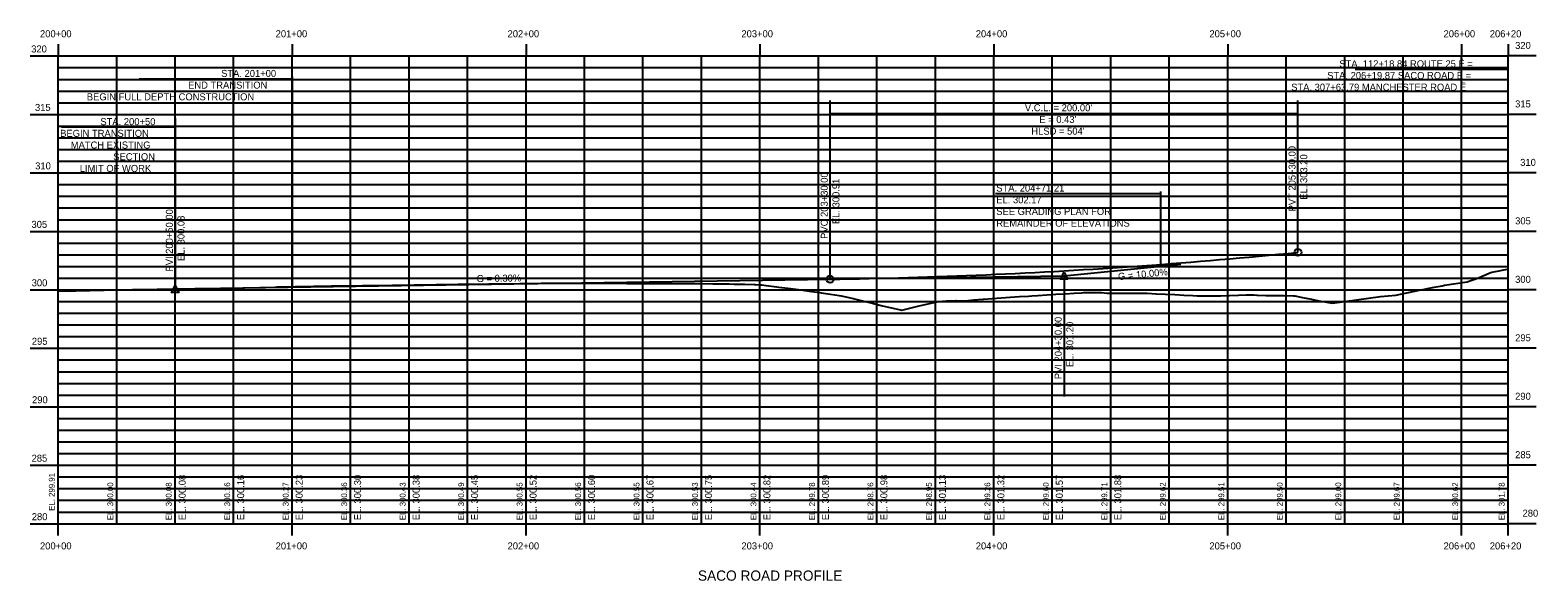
# Model space of a CAD drawing. Extents: x 916064 to 2216531, y 210276 to 327856.
# Drawn here: x 916107 to 916752, y 326074 to 326309 of the extents above; entities that cross this region are included whole.
import ezdxf

# ---------------------------------------------------------------- set-up
doc = ezdxf.new("R2010")
doc.units = 0
for name, color, linetype in [('ANNOTATION', 7, 'Continuous'), ('BARRIER', 7, 'Continuous'), ('D_Roadway_Centerline', 7, 'Continuous'), ('D_Roadway_Centerline_Bearings', 7, 'Continuous'), ('D_Roadway_Centerline_CurveData', 7, 'Continuous'), ('D_Roadway_Centerline_Flags', 7, 'Continuous'), ('D_Roadway_Centerline_Text', 7, 'Continuous'), ('D_Roadway_Edge_Pavement', 7, 'Continuous')]:
    doc.layers.add(name, color=color, linetype=linetype)

msp = doc.modelspace()

# ---------------------------------------------------------------- linework, layer by layer
at = {"layer": 'ANNOTATION'}
msp.add_line((916169.09, 326198.47), (916449.09, 326202.6), dxfattribs=at)
for points in [[(916449.09, 326202.6), (916453.26, 326202.66), (916457.42, 326202.73), (916461.59, 326202.81), (916465.76, 326202.9), (916469.92, 326203), (916474.09, 326203.1), (916478.26, 326203.21), (916482.42, 326203.33), (916486.59, 326203.45), (916490.76, 326203.58), (916494.92, 326203.72), (916499.09, 326203.87), (916503.26, 326204.02), (916507.42, 326204.18), (916511.59, 326204.35), (916515.76, 326204.53), (916519.92, 326204.71), (916524.09, 326204.9), (916528.26, 326205.1), (916532.42, 326205.31), (916536.59, 326205.52), (916540.76, 326205.74), (916544.92, 326205.97), (916553.26, 326206.45), (916557.42, 326206.7), (916561.59, 326206.95), (916565.76, 326207.22), (916569.92, 326207.49), (916574.09, 326207.77), (916578.26, 326208.06), (916582.42, 326208.35), (916586.59, 326208.65), (916590.49, 326208.94)], [(916590.49, 326208.94), (916590.76, 326208.96), (916594.92, 326209.28), (916599.09, 326209.6), (916603.26, 326209.94), (916607.42, 326210.28), (916611.59, 326210.62), (916615.76, 326210.98), (916619.92, 326211.34), (916624.09, 326211.71), (916628.26, 326212.08), (916632.42, 326212.46), (916636.59, 326212.86), (916640.76, 326213.25), (916644.92, 326213.66), (916649.09, 326214.07)]]:
    msp.add_lwpolyline(points, dxfattribs=at)
at = {"layer": 'D_Roadway_Centerline'}
for p, q in [((916107.09, 326298.06), (916119.09, 326298.06)), ((916107.09, 326298.06), (916119.09, 326298.06)), ((916119.09, 326303.06), (916119.09, 326298.06)), ((916119.09, 326298.06), (916738.96, 326298.06)), ((916119.09, 326098.06), (916119.09, 326298.06)), ((916219.09, 326303.06), (916219.09, 326298.06)), ((916219.09, 326098.06), (916219.09, 326298.06)), ((916319.09, 326303.06), (916319.09, 326298.06)), ((916319.09, 326098.06), (916319.09, 326298.06)), ((916419.09, 326303.06), (916419.09, 326298.06)), ((916419.09, 326098.06), (916419.09, 326298.06)), ((916519.09, 326303.06), (916519.09, 326298.06)), ((916519.09, 326098.06), (916519.09, 326298.06)), ((916619.09, 326303.06), (916619.09, 326298.06)), ((916619.09, 326098.06), (916619.09, 326298.06)), ((916719.09, 326303.06), (916719.09, 326298.06)), ((916719.09, 326098.06), (916719.09, 326298.06)), ((916738.96, 326303.06), (916738.96, 326298.06)), ((916738.96, 326098.06), (916738.96, 326298.06)), ((916750.96, 326298.06), (916738.96, 326298.06)), ((916750.96, 326298.06), (916738.96, 326298.06)), ((916107.09, 326273.06), (916119.09, 326273.06)), ((916119.09, 326273.06), (916738.96, 326273.06)), ((916750.96, 326273.06), (916738.96, 326273.06)), ((916107.09, 326248.06), (916119.09, 326248.06)), ((916119.09, 326248.06), (916738.96, 326248.06)), ((916750.96, 326248.06), (916738.96, 326248.06)), ((916107.09, 326223.06), (916119.09, 326223.06)), ((916119.09, 326223.06), (916738.96, 326223.06)), ((916750.96, 326223.06), (916738.96, 326223.06)), ((916107.09, 326198.06), (916119.09, 326198.06)), ((916119.09, 326198.06), (916738.96, 326198.06)), ((916750.96, 326198.06), (916738.96, 326198.06)), ((916107.09, 326173.06), (916119.09, 326173.06)), ((916119.09, 326173.06), (916738.96, 326173.06)), ((916750.96, 326173.06), (916738.96, 326173.06)), ((916107.09, 326148.06), (916119.09, 326148.06)), ((916119.09, 326148.06), (916738.96, 326148.06)), ((916750.96, 326148.06), (916738.96, 326148.06)), ((916107.09, 326123.06), (916119.09, 326123.06)), ((916119.09, 326123.06), (916738.96, 326123.06)), ((916750.96, 326123.06), (916738.96, 326123.06)), ((916107.09, 326098.06), (916119.09, 326098.06)), ((916119.09, 326098.06), (916738.96, 326098.06)), ((916119.09, 326093.06), (916119.09, 326098.06)), ((916219.09, 326093.06), (916219.09, 326098.06)), ((916319.09, 326093.06), (916319.09, 326098.06)), ((916419.09, 326093.06), (916419.09, 326098.06)), ((916519.09, 326093.06), (916519.09, 326098.06)), ((916619.09, 326093.06), (916619.09, 326098.06)), ((916719.09, 326093.06), (916719.09, 326098.06)), ((916750.96, 326098.06), (916738.96, 326098.06)), ((916738.96, 326093.06), (916738.96, 326098.06))]:
    msp.add_line(p, q, dxfattribs=at)
at = {"layer": 'D_Roadway_Centerline_Bearings'}
for p, q in [((916449.09, 326202.6), (916449.09, 326279)), ((916649.09, 326214.07), (916649.09, 326279)), ((916449.09, 326227.6), (916449.09, 326275.2)), ((916169.09, 326198.47), (916169.09, 326246.06)), ((916649.09, 326214.07), (916649.09, 326239.07)), ((916449.09, 326202.6), (916449.09, 326227.6)), ((916549.09, 326204.07), (916599.09, 326209.07)), ((916499.09, 326203.33), (916549.09, 326204.07)), ((916549.09, 326204.07), (916549.09, 326152.47))]:
    msp.add_line(p, q, dxfattribs=at)
msp.add_lwpolyline([(916449.09, 326273.42), (916649.09, 326273.42)], dxfattribs=at)
for points in [[(916549.09, 326205.57), (916550.59, 326202.57), (916547.59, 326202.57)], [(916169.09, 326199.97), (916170.59, 326196.97), (916167.59, 326196.97)]]:
    msp.add_lwpolyline(points, close=True, dxfattribs=at)
for centre in [(916649.09, 326214.07), (916449.09, 326202.6)]:
    msp.add_circle(centre, 1.5, dxfattribs=at)
at = {"layer": 'D_Roadway_Centerline_Flags'}
msp.add_lwpolyline([(916119.09, 326197.59), (916124.98, 326197.68), (916126.58, 326197.68), (916150.89, 326198.19), (916152.14, 326198.22), (916153.33, 326198.23), (916177.49, 326198.59), (916178.18, 326198.59), (916192.26, 326198.84), (916211.71, 326199.25), (916212.15, 326199.27), (916212.66, 326199.28), (916235.99, 326199.75), (916236.3, 326199.76), (916262.05, 326200.11), (916289.87, 326200.46), (916316.43, 326200.76), (916317.93, 326200.78), (916318.19, 326200.78), (916321.02, 326200.81), (916324.13, 326200.84), (916325.6, 326200.85), (916330.18, 326200.86), (916334.76, 326200.86), (916339.34, 326200.86), (916343.92, 326200.86), (916345.96, 326200.85), (916348.5, 326200.86), (916353.08, 326200.85), (916357.66, 326200.85), (916362.24, 326200.84), (916366.11, 326200.82), (916366.82, 326200.82), (916371.4, 326200.79), (916373.46, 326200.77), (916375.98, 326200.78), (916380.56, 326200.8), (916385.14, 326200.82), (916386.98, 326200.83), (916389.72, 326200.79), (916394.3, 326200.73), (916398.89, 326200.65), (916400.65, 326200.62), (916403.47, 326200.6), (916405.89, 326200.58), (916408.05, 326200.55), (916412.63, 326200.47), (916416.81, 326200.39), (916417.21, 326200.37), (916419.11, 326200.24), (916419.94, 326200.2), (916421.79, 326199.97), (916426.37, 326199.36), (916427.16, 326199.25), (916430.95, 326198.78), (916435.53, 326198.18), (916440.11, 326197.55), (916444.69, 326196.89), (916445.2, 326196.82), (916449.27, 326196.21), (916453, 326195.62), (916453.85, 326195.47), (916454.6, 326195.34), (916458.43, 326194.45), (916463.01, 326193.35), (916467.59, 326192.22), (916471.5, 326191.26), (916475.4, 326190.34), (916479.22, 326189.46), (916479.3, 326189.44), (916479.73, 326189.34), (916480.38, 326189.51), (916483.21, 326190.22), (916487.11, 326191.18), (916491.01, 326192.09), (916494.92, 326192.98), (916495.39, 326193.08), (916498.82, 326193.29), (916502.72, 326193.51), (916502.95, 326193.53), (916506.63, 326193.41), (916506.75, 326193.41), (916510.53, 326193.72), (916514.43, 326194.04), (916514.86, 326194.08), (916518.34, 326194.33), (916522.24, 326194.6), (916526.14, 326194.87), (916530.05, 326195.14), (916533.95, 326195.4), (916535.28, 326195.49), (916537.85, 326195.66), (916541.76, 326195.91), (916545.66, 326196.16), (916549.56, 326196.4), (916553.47, 326196.64), (916556.68, 326196.84), (916557.37, 326196.85), (916561.27, 326196.92), (916564.78, 326196.97), (916565.18, 326196.92), (916567.36, 326196.63), (916569.08, 326196.63), (916571.18, 326196.62), (916572.98, 326196.63), (916576.89, 326196.64), (916580.79, 326196.64), (916583.36, 326196.64), (916584.69, 326196.58), (916588.54, 326196.4), (916588.6, 326196.39), (916592.5, 326196.22), (916596.4, 326196.03), (916600.31, 326195.84), (916604.21, 326195.65), (916606.08, 326195.55), (916608.11, 326195.54), (916612.02, 326195.5), (916615.92, 326195.47), (916615.95, 326195.47), (916619.82, 326195.63), (916623.73, 326195.79), (916626.97, 326195.91), (916627.63, 326195.92), (916630.18, 326195.97), (916631.53, 326195.75), (916631.76, 326195.71), (916635.44, 326195.68), (916639.34, 326195.63), (916643.24, 326195.57), (916647.15, 326195.5), (916647.76, 326195.49), (916651.05, 326194.85), (916654.95, 326194.06), (916658.01, 326193.42), (916663.94, 326192.33), (916684.38, 326195.26), (916691, 326195.74), (916701.03, 326197.95), (916707.41, 326199.26), (916710.74, 326199.82), (916711.81, 326200.04), (916721.42, 326201.54), (916722.95, 326201.99), (916725.18, 326202.78), (916729.55, 326204.55), (916731.18, 326205.35), (916732.03, 326205.61), (916735.16, 326206.24), (916736.36, 326206.44), (916738.66, 326206.92), (916738.96, 326206.98)], dxfattribs=at)
at = {"layer": 'D_Roadway_Centerline_Text'}
for p, q in [((916144.09, 326098.06), (916144.09, 326298.06)), ((916169.09, 326098.06), (916169.09, 326298.06)), ((916194.09, 326098.06), (916194.09, 326298.06)), ((916244.09, 326098.06), (916244.09, 326298.06)), ((916269.09, 326098.06), (916269.09, 326298.06)), ((916294.09, 326098.06), (916294.09, 326298.06)), ((916344.09, 326098.06), (916344.09, 326298.06)), ((916369.09, 326098.06), (916369.09, 326298.06)), ((916394.09, 326098.06), (916394.09, 326298.06)), ((916444.09, 326098.06), (916444.09, 326298.06)), ((916469.09, 326098.06), (916469.09, 326298.06)), ((916494.09, 326098.06), (916494.09, 326298.06)), ((916544.09, 326098.06), (916544.09, 326298.06)), ((916569.09, 326098.06), (916569.09, 326298.06)), ((916594.09, 326098.06), (916594.09, 326298.06)), ((916644.09, 326098.06), (916644.09, 326298.06)), ((916669.09, 326098.06), (916669.09, 326298.06)), ((916694.09, 326098.06), (916694.09, 326298.06)), ((916119.09, 326293.06), (916738.96, 326293.06)), ((916119.09, 326288.06), (916738.96, 326288.06)), ((916119.09, 326283.06), (916738.96, 326283.06)), ((916119.09, 326278.06), (916738.96, 326278.06)), ((916119.09, 326268.06), (916738.96, 326268.06)), ((916119.09, 326263.06), (916738.96, 326263.06)), ((916119.09, 326258.06), (916738.96, 326258.06)), ((916119.09, 326253.06), (916738.96, 326253.06)), ((916119.09, 326243.06), (916738.96, 326243.06)), ((916119.09, 326238.06), (916738.96, 326238.06)), ((916119.09, 326233.06), (916738.96, 326233.06)), ((916119.09, 326228.06), (916738.96, 326228.06)), ((916119.09, 326218.06), (916738.96, 326218.06)), ((916119.09, 326213.06), (916738.96, 326213.06)), ((916119.09, 326208.06), (916738.96, 326208.06)), ((916119.09, 326203.06), (916738.96, 326203.06)), ((916119.09, 326193.06), (916738.96, 326193.06)), ((916119.09, 326188.06), (916738.96, 326188.06)), ((916119.09, 326183.06), (916738.96, 326183.06)), ((916119.09, 326178.06), (916738.96, 326178.06)), ((916119.09, 326168.06), (916738.96, 326168.06)), ((916119.09, 326163.06), (916738.96, 326163.06)), ((916119.09, 326158.06), (916738.96, 326158.06)), ((916119.09, 326153.06), (916738.96, 326153.06)), ((916119.09, 326143.06), (916738.96, 326143.06)), ((916119.09, 326138.06), (916738.96, 326138.06)), ((916119.09, 326133.06), (916738.96, 326133.06)), ((916119.09, 326128.06), (916738.96, 326128.06)), ((916119.09, 326118.06), (916738.96, 326118.06)), ((916119.09, 326113.06), (916738.96, 326113.06)), ((916119.09, 326108.06), (916738.96, 326108.06)), ((916119.09, 326103.06), (916738.96, 326103.06))]:
    msp.add_line(p, q, dxfattribs=at)
at = {"layer": 'D_Roadway_Edge_Pavement'}
for p, q in [((916673.62, 326292.43), (916738.96, 326292.43)), ((916153.75, 326288.32), (916219.09, 326288.32)), ((916219.09, 326289.07), (916219.09, 326199.2)), ((916120.55, 326267.71), (916169.09, 326267.71)), ((916169.09, 326271.48), (916169.09, 326198.47)), ((916590.3, 326240.04), (916590.3, 326208.93)), ((916519.76, 326239.29), (916590.3, 326239.29))]:
    msp.add_line(p, q, dxfattribs=at)

# ---------------------------------------------------------------- texts
at = {"layer": 'BARRIER'}
for s, p in [('EL. 300.08', (916173.59, 326099.56)), ('EL. 300.16', (916198.59, 326099.56)), ('EL. 300.23', (916223.59, 326099.56)), ('EL. 300.30', (916248.59, 326099.56)), ('EL. 300.38', (916273.59, 326099.56)), ('EL. 300.45', (916298.59, 326099.56)), ('EL. 300.52', (916323.59, 326099.56)), ('EL. 300.60', (916348.59, 326099.56)), ('EL. 300.67', (916373.59, 326099.56)), ('EL. 300.75', (916398.59, 326099.56)), ('EL. 300.82', (916423.59, 326099.56)), ('EL. 300.89', (916448.59, 326099.56)), ('EL. 300.98', (916473.59, 326099.56)), ('EL. 301.13', (916498.59, 326099.56)), ('EL. 301.32', (916523.59, 326099.56)), ('EL. 301.57', (916548.59, 326099.56)), ('EL. 301.88', (916573.59, 326099.56))]:
    msp.add_text(s, height=3, rotation=90, dxfattribs=at).set_placement(p)
at = {"layer": 'D_Roadway_Centerline_Bearings'}
for s, p in [("V.C.L. = 200.00'", (916532.36, 326274.42)), ("E = 0.43'", (916538.54, 326269.42)), ("HLSD = 504'", (916535.13, 326264.42))]:
    msp.add_text(s, height=3, dxfattribs=at).set_placement(p)
for s, rotation, p in [('PVT 205+30.00', 90, (916648.09, 326231.58)), ('EL. 303.20', 90, (916653.09, 326236.61)), ('PVC 203+30.00', 90, (916448.09, 326219.86)), ('EL. 300.91', 90, (916453.09, 326226.18)), ('PVI 200+50.00', 90, (916168.09, 326205.88)), ('EL. 300.08', 90, (916173.09, 326210.37)), ('G = 0.30%', 0.84525, (916297.98, 326201.37)), ('PVI 204+30.00', 90, (916548.09, 326159.86)), ('EL. 301.20', 90, (916553.09, 326165.01))]:
    msp.add_text(s, height=3, rotation=rotation, dxfattribs=at).set_placement(p)
at = {"layer": 'D_Roadway_Centerline_CurveData'}
for s, height, p in [('200+00', 3, (916111.3, 326306.06)), ('201+00', 3, (916212.05, 326306.06)), ('202+00', 3, (916311.2, 326306.06)), ('203+00', 3, (916411.17, 326306.06)), ('204+00', 3, (916511.36, 326306.06)), ('205+00', 3, (916611.25, 326306.06)), ('206+00', 3, (916711.36, 326306.06)), ('206+20', 3, (916731.12, 326306.06)), ('320', 3, (916107.53, 326299.56)), ('320', 3, (916107.53, 326299.56)), ('320', 3, (916741.96, 326301.06)), ('320', 3, (916741.96, 326301.06)), ('315', 3, (916741.96, 326276.06)), ('315', 3, (916109.16, 326274.56)), ('310', 3, (916744.13, 326251.06)), ('310', 3, (916109.24, 326249.56)), ('305', 3, (916107.66, 326224.56)), ('305', 3, (916741.96, 326226.06)), ('300', 3, (916107.74, 326199.56)), ('300', 3, (916741.96, 326201.06)), ('295', 3, (916107.82, 326174.56)), ('295', 3, (916741.96, 326176.06)), ('290', 3, (916107.9, 326149.56)), ('290', 3, (916741.96, 326151.06)), ('285', 3, (916107.71, 326124.56)), ('285', 3, (916741.96, 326126.06)), ('280', 3, (916107.79, 326099.56)), ('280', 3, (916745.13, 326101.06)), ('200+00', 3, (916111.3, 326087.06)), ('201+00', 3, (916212.05, 326087.06)), ('202+00', 3, (916311.2, 326087.06)), ('203+00', 3, (916411.17, 326087.06)), ('204+00', 3, (916511.36, 326087.06)), ('205+00', 3, (916611.25, 326087.06)), ('206+00', 3, (916711.36, 326087.06)), ('206+20', 3, (916731.12, 326087.06)), ('SACO ROAD PROFILE', 4.3749, (916392.58, 326073.68))]:
    msp.add_text(s, height=height, dxfattribs=at).set_placement(p)
at = {"layer": 'D_Roadway_Edge_Pavement'}
for s, p in [('STA. 201+00', (916188.72, 326289.1)), ('STA. 206+19.87 SACO ROAD Ë =', (916661.59, 326288.21)), ('STA. 112+18.84 ROUTE 25 Ë =', (916666.79, 326293.21)), ('END TRANSITION', (916174.62, 326284.1)), ('STA. 307+63.79 MANCHESTER ROAD Ë', (916646.21, 326283.21)), ('BEGIN FULL DEPTH CONSTRUCTION', (916131.32, 326279.1)), ('BEGIN TRANSITION', (916119.92, 326263.48)), ('STA. 200+50', (916137.11, 326268.48)), ('MATCH EXISTING', (916124.45, 326258.48)), (' SECTION', (916141.51, 326253.48)), ('LIMIT OF WORK', (916128.29, 326248.48)), ('STA. 204+71.21', (916520.13, 326240.07)), ('EL. 302.17', (916520.13, 326235.07)), ('SEE GRADING PLAN FOR', (916520.13, 326230.07)), ('REMAINDER OF ELEVATIONS', (916520.13, 326225.07))]:
    msp.add_text(s, height=3, dxfattribs=at).set_placement(p)
for s, height, rotation, p in [('G = 10.00%', 3, 5.71059, (916572.35, 326202.21)), ('EL. 299.91', 2.5, 90, (916117.59, 326103.56)), ('EL. 300.00', 2.5, 90, (916142.59, 326099.56)), ('EL. 300.08', 2.5, 90, (916167.59, 326099.56)), ('EL. 300.16', 2.5, 90, (916192.59, 326099.56)), ('EL. 300.27', 2.5, 90, (916217.59, 326099.56)), ('EL. 300.36', 2.5, 90, (916242.59, 326099.56)), ('EL. 300.43', 2.5, 90, (916267.59, 326099.56)), ('EL. 300.49', 2.5, 90, (916292.59, 326099.56)), ('EL. 300.55', 2.5, 90, (916317.59, 326099.56)), ('EL. 300.56', 2.5, 90, (916342.59, 326099.56)), ('EL. 300.55', 2.5, 90, (916367.59, 326099.56)), ('EL. 300.53', 2.5, 90, (916392.59, 326099.56)), ('EL. 300.44', 2.5, 90, (916417.59, 326099.56)), ('EL. 299.78', 2.5, 90, (916442.59, 326099.56)), ('EL. 298.76', 2.5, 90, (916467.59, 326099.56)), ('EL. 298.95', 2.5, 90, (916492.59, 326099.56)), ('EL. 299.26', 2.5, 90, (916517.59, 326099.56)), ('EL. 299.60', 2.5, 90, (916542.59, 326099.56)), ('EL. 299.71', 2.5, 90, (916567.59, 326099.56)), ('EL. 299.62', 2.5, 90, (916592.59, 326099.56)), ('EL. 299.51', 2.5, 90, (916617.59, 326099.56)), ('EL. 299.50', 2.5, 90, (916642.59, 326099.56)), ('EL. 299.00', 2.5, 90, (916667.59, 326099.56)), ('EL. 299.67', 2.5, 90, (916692.59, 326099.56)), ('EL. 300.62', 2.5, 90, (916717.59, 326099.56)), ('EL. 301.78', 2.5, 90, (916737.46, 326099.56))]:
    msp.add_text(s, height=height, rotation=rotation, dxfattribs=at).set_placement(p)

doc.saveas('drawing.dxf')
